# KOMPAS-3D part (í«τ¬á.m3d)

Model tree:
1. Эскиз:1
2. Операция выдавливания:1
     Расстояние 1 = 25.6; Расстояние 2 = 1
3. Эскиз:2
4. Операция выдавливания:2
     Расстояние 1 = 25.6; Расстояние 2 = 1.6
5. Эскиз:3
6. Вырезать элемент выдавливания:1
     Расстояние 1 = 1
7. Эскиз:4
8. Вырезать элемент выдавливания:2
     Расстояние 1 = 24
9. Эскиз:5
10. Операция вращения:1
     Угол 1 = 360
11. Зеркальный массив:1  (with: Операция выдавливания:1, Операция выдавливания:2, Вырезать элемент выдавливания:1, Вырезать элемент выдавливания:2, Операция вращения:1)  (labels: Экземпляр ( 1 ); Экземпляр ( 2 ))
12. Эскиз:6
13. Операция выдавливания:3
     Расстояние 1 = 0.5; Расстояние 2 = 1.6
14. Скругление:1
     Радиус = 0.5
15. Эскиз:7
16. Операция выдавливания:4
     Расстояние 1 = 0.5; Расстояние 2 = 1.6
17. Скругление:2
     Радиус = 0.5
18. Эскиз:8
19. Операция выдавливания:5
     Расстояние 1 = 0.5; Расстояние 2 = 1.6
20. Скругление:3
     Радиус = 0.3
21. Эскиз:9
22. Операция выдавливания:6
     Расстояние 1 = 0.5; Расстояние 2 = 1.6
23. Эскиз:10
24. Операция выдавливания:7
     Расстояние 1 = 1; Расстояние 2 = 1.6

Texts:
  Сплав АЛ8  ГОСТ 1583-93
  Экземпляр ( 1 )
  Экземпляр ( 2 )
